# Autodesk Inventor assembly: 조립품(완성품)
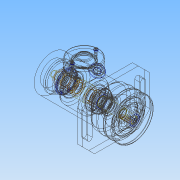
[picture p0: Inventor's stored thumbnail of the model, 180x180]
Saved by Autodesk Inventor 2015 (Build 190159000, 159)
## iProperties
Created: 2017-10
Part Number: 조립품(완성품)
Document SubType Name: Assembly
Designer: Administrator
Author: Administrator
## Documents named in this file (18)
- C:\Users\Administrator\Desktop\471007V1007\조립품(완성품).iam
- C:\Users\Administrator\Desktop\471007V1007\부품(완성품).ipt
- C:\Users\Administrator\Desktop\471007V1007\베어링 15 x 35 x 11.ipt
- C:\Users\Administrator\Desktop\471007V1007\멈춤링 35x1.6.ipt
- C:\Users\Administrator\Desktop\471007V1007\부시2.ipt
- C:\Users\Administrator\Desktop\471007V1007\와셔 10x21.ipt
- C:\Users\Administrator\Desktop\471007V1007\축.ipt
- C:\Users\Administrator\Desktop\471007V1007\부시1.ipt
- C:\Users\Administrator\Desktop\471007V1007\너트 M10.ipt
- C:\Users\Administrator\Desktop\471007V1007\멈춤링 15 x 1.ipt
- C:\Users\Administrator\Desktop\471007V1007\오일 실 15 25 7.ipt
- C:\Users\Administrator\Desktop\471007V1007\키 4 x 4 x 18.ipt
- C:\Users\Administrator\Desktop\471007V1007\V-벨트풀리.ipt
- C:\Users\Administrator\Desktop\471007V1007\와셔 4x16.ipt
- C:\Users\Administrator\Desktop\471007V1007\볼트 M4 x 10.ipt
- C:\Users\Administrator\Desktop\471007V1007\탑 커버.ipt
- C:\Users\Administrator\Desktop\471007V1007\와셔 3x6.ipt
- C:\Users\Administrator\Desktop\471007V1007\십자볼트 M3 x 10.ipt
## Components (2 placed, 2 different names)
1. V-벨트풀리:1 — 각도:2
2. ISO 4017 M4 x 10:1
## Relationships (1: Angle 1)
- 각도:2 [Angle]: V-벨트풀리:1
